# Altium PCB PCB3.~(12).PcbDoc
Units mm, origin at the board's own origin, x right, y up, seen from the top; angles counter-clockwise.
Board outline 50 x 50 mm, 4 copper layers (Top Layer, Internal Plane 1, Internal Plane 2, Bottom Layer), stack 0.462 mm thick; 11 components, 12 nets, 36 pads, 0 vias.
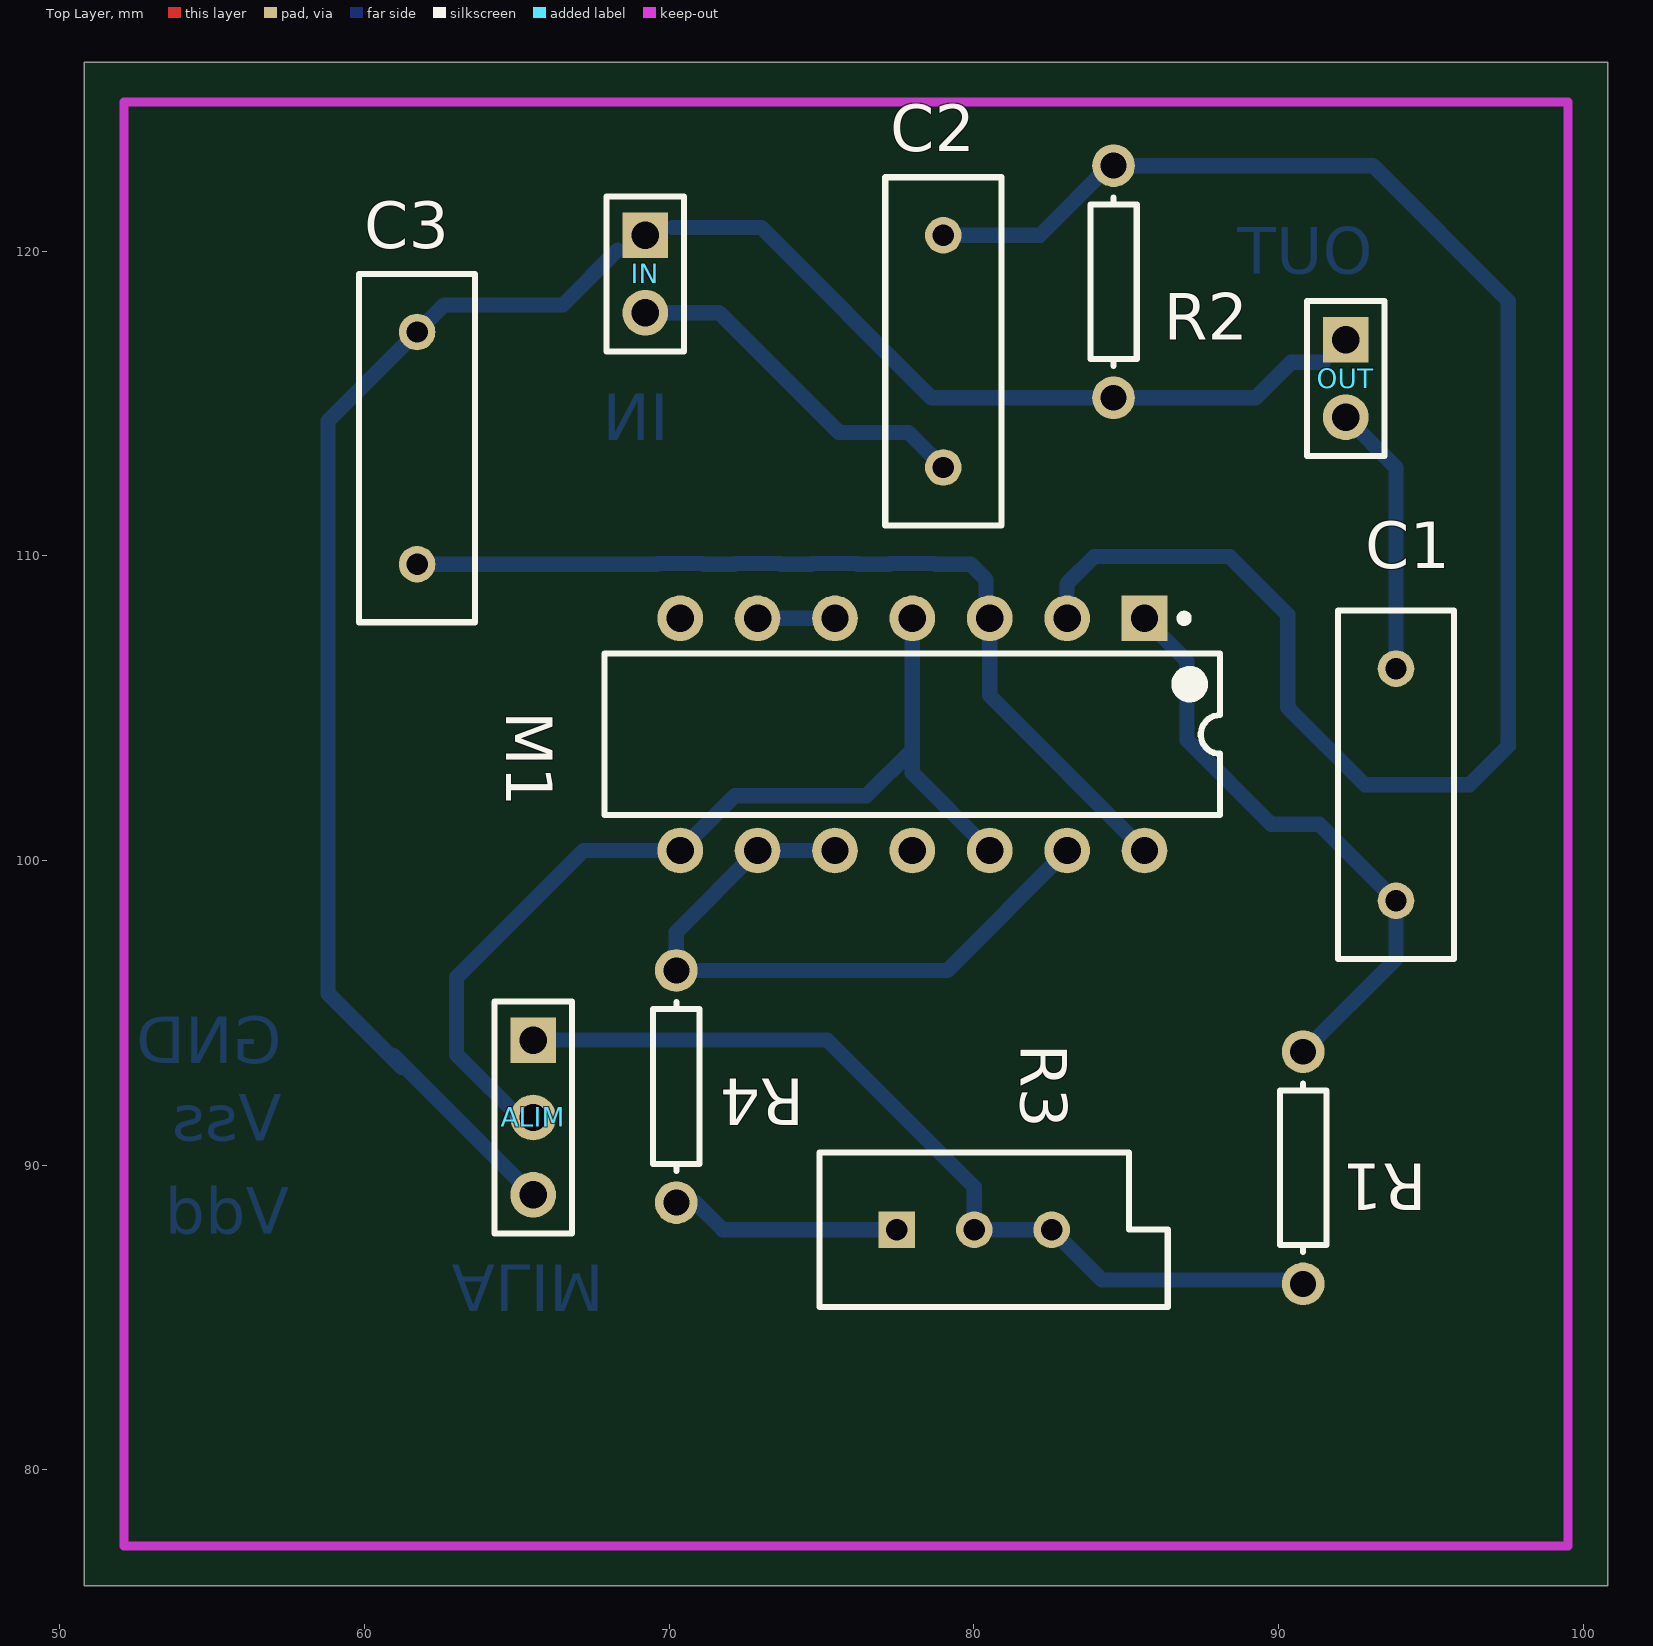
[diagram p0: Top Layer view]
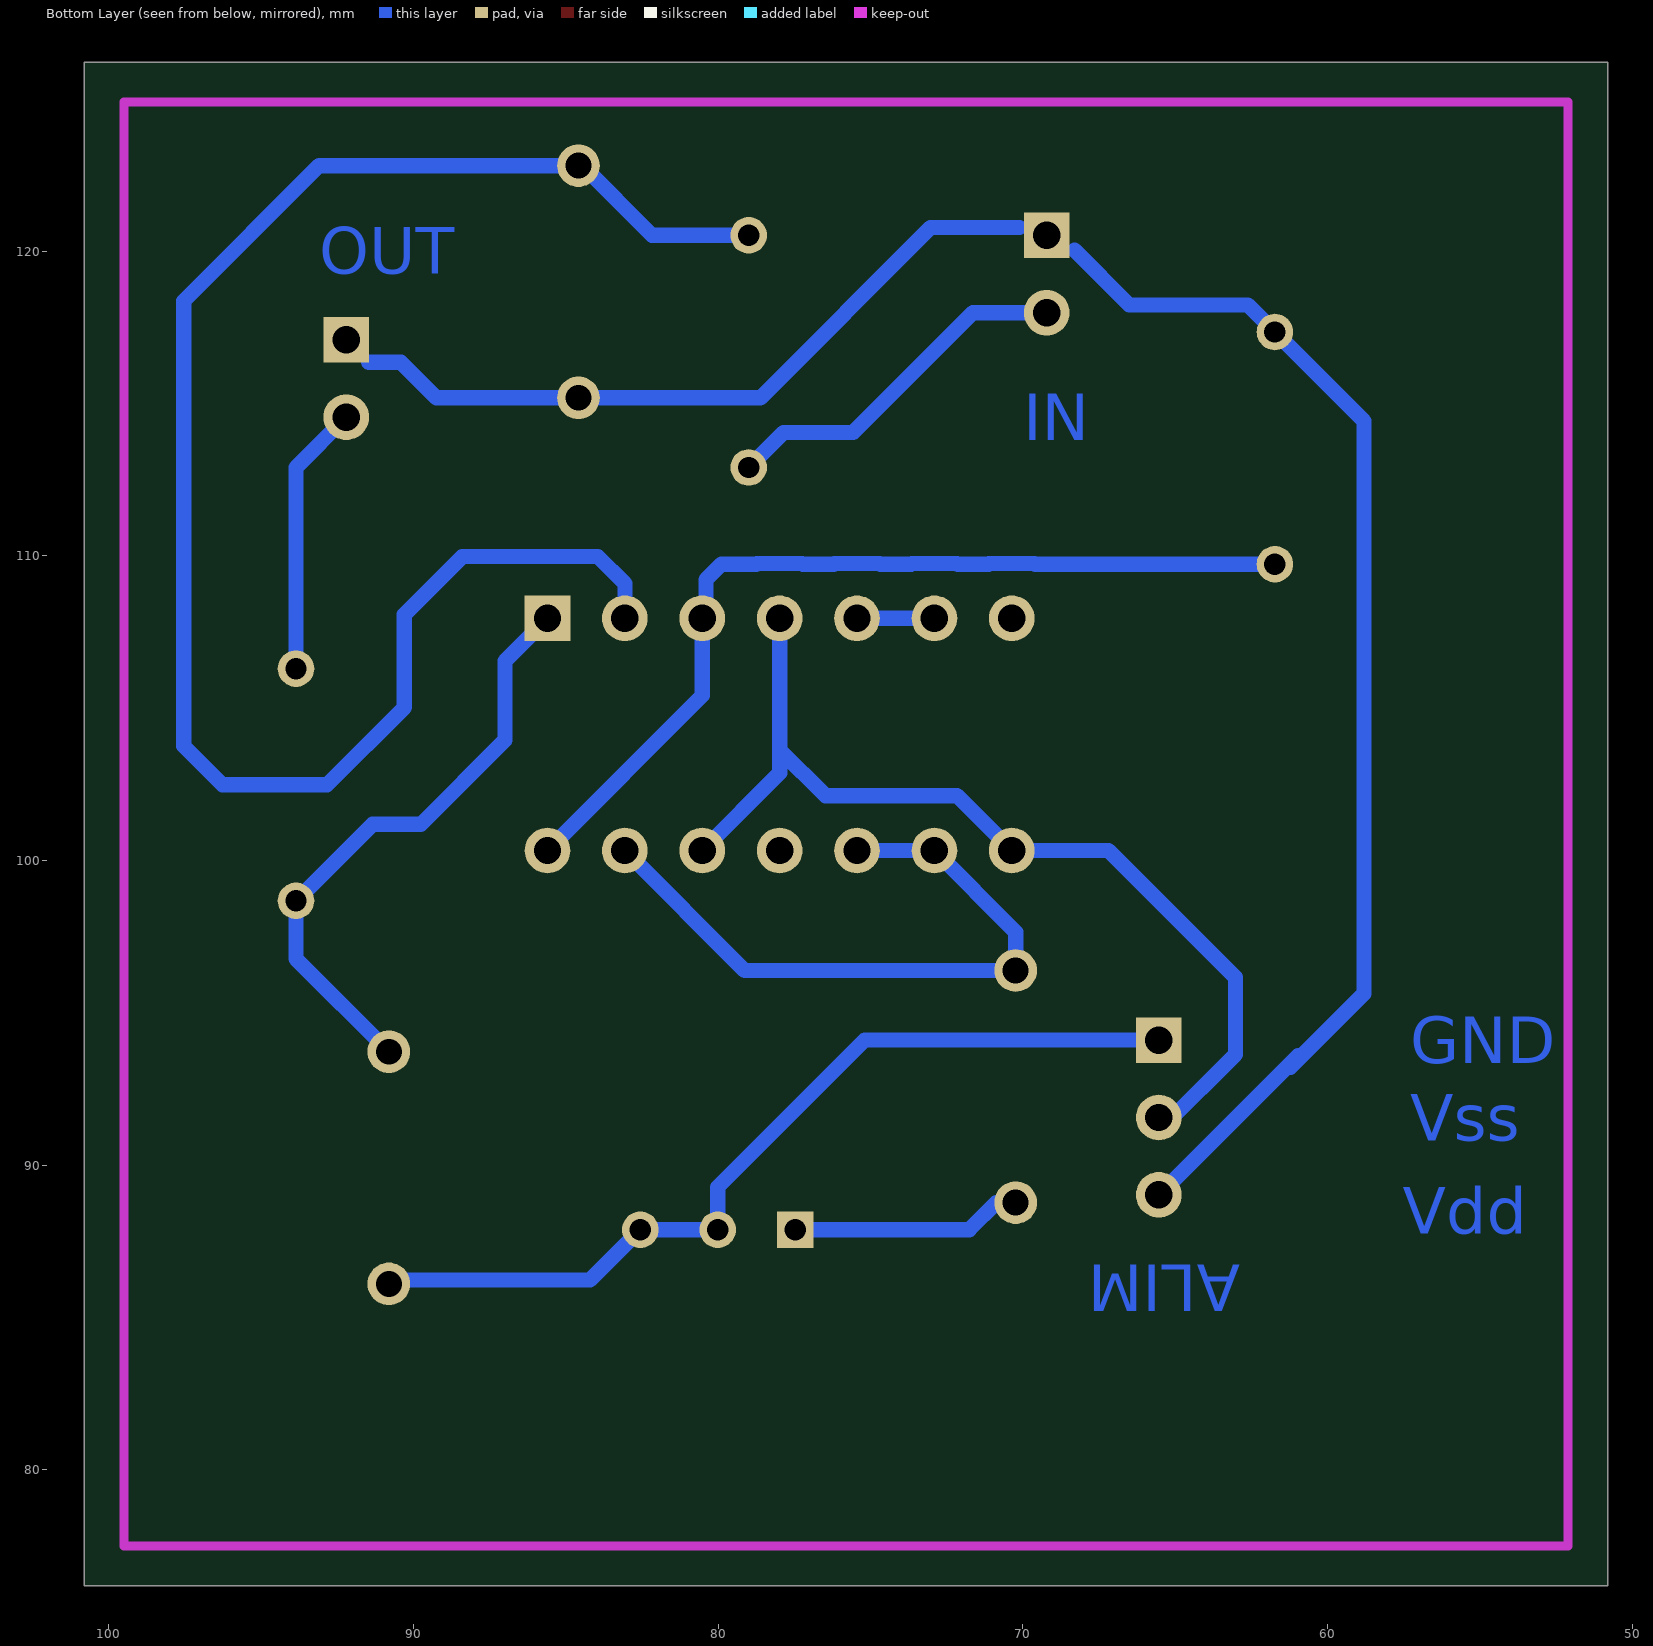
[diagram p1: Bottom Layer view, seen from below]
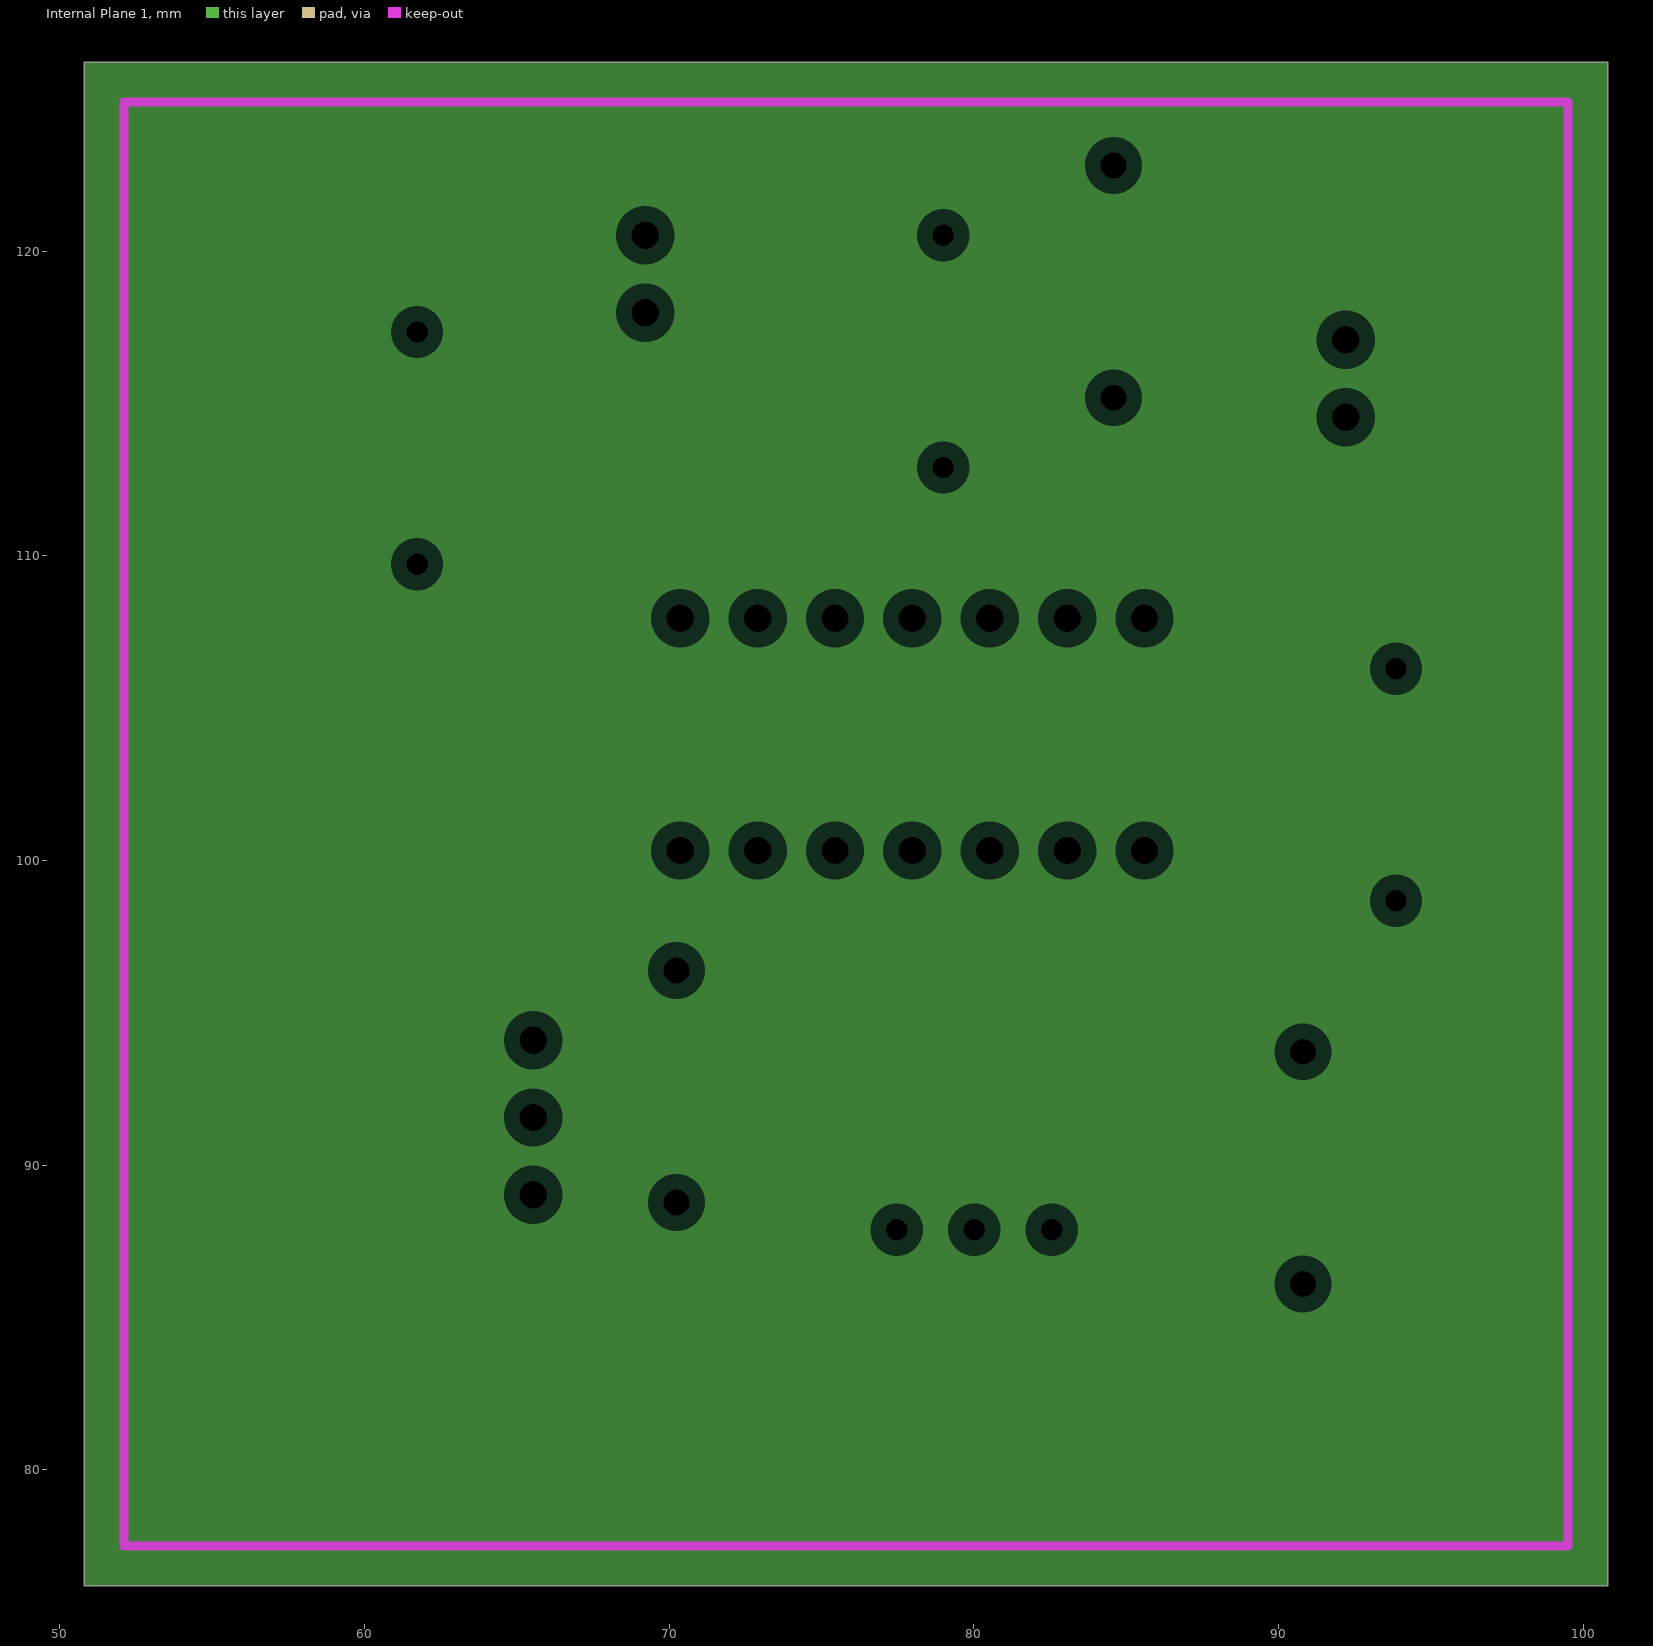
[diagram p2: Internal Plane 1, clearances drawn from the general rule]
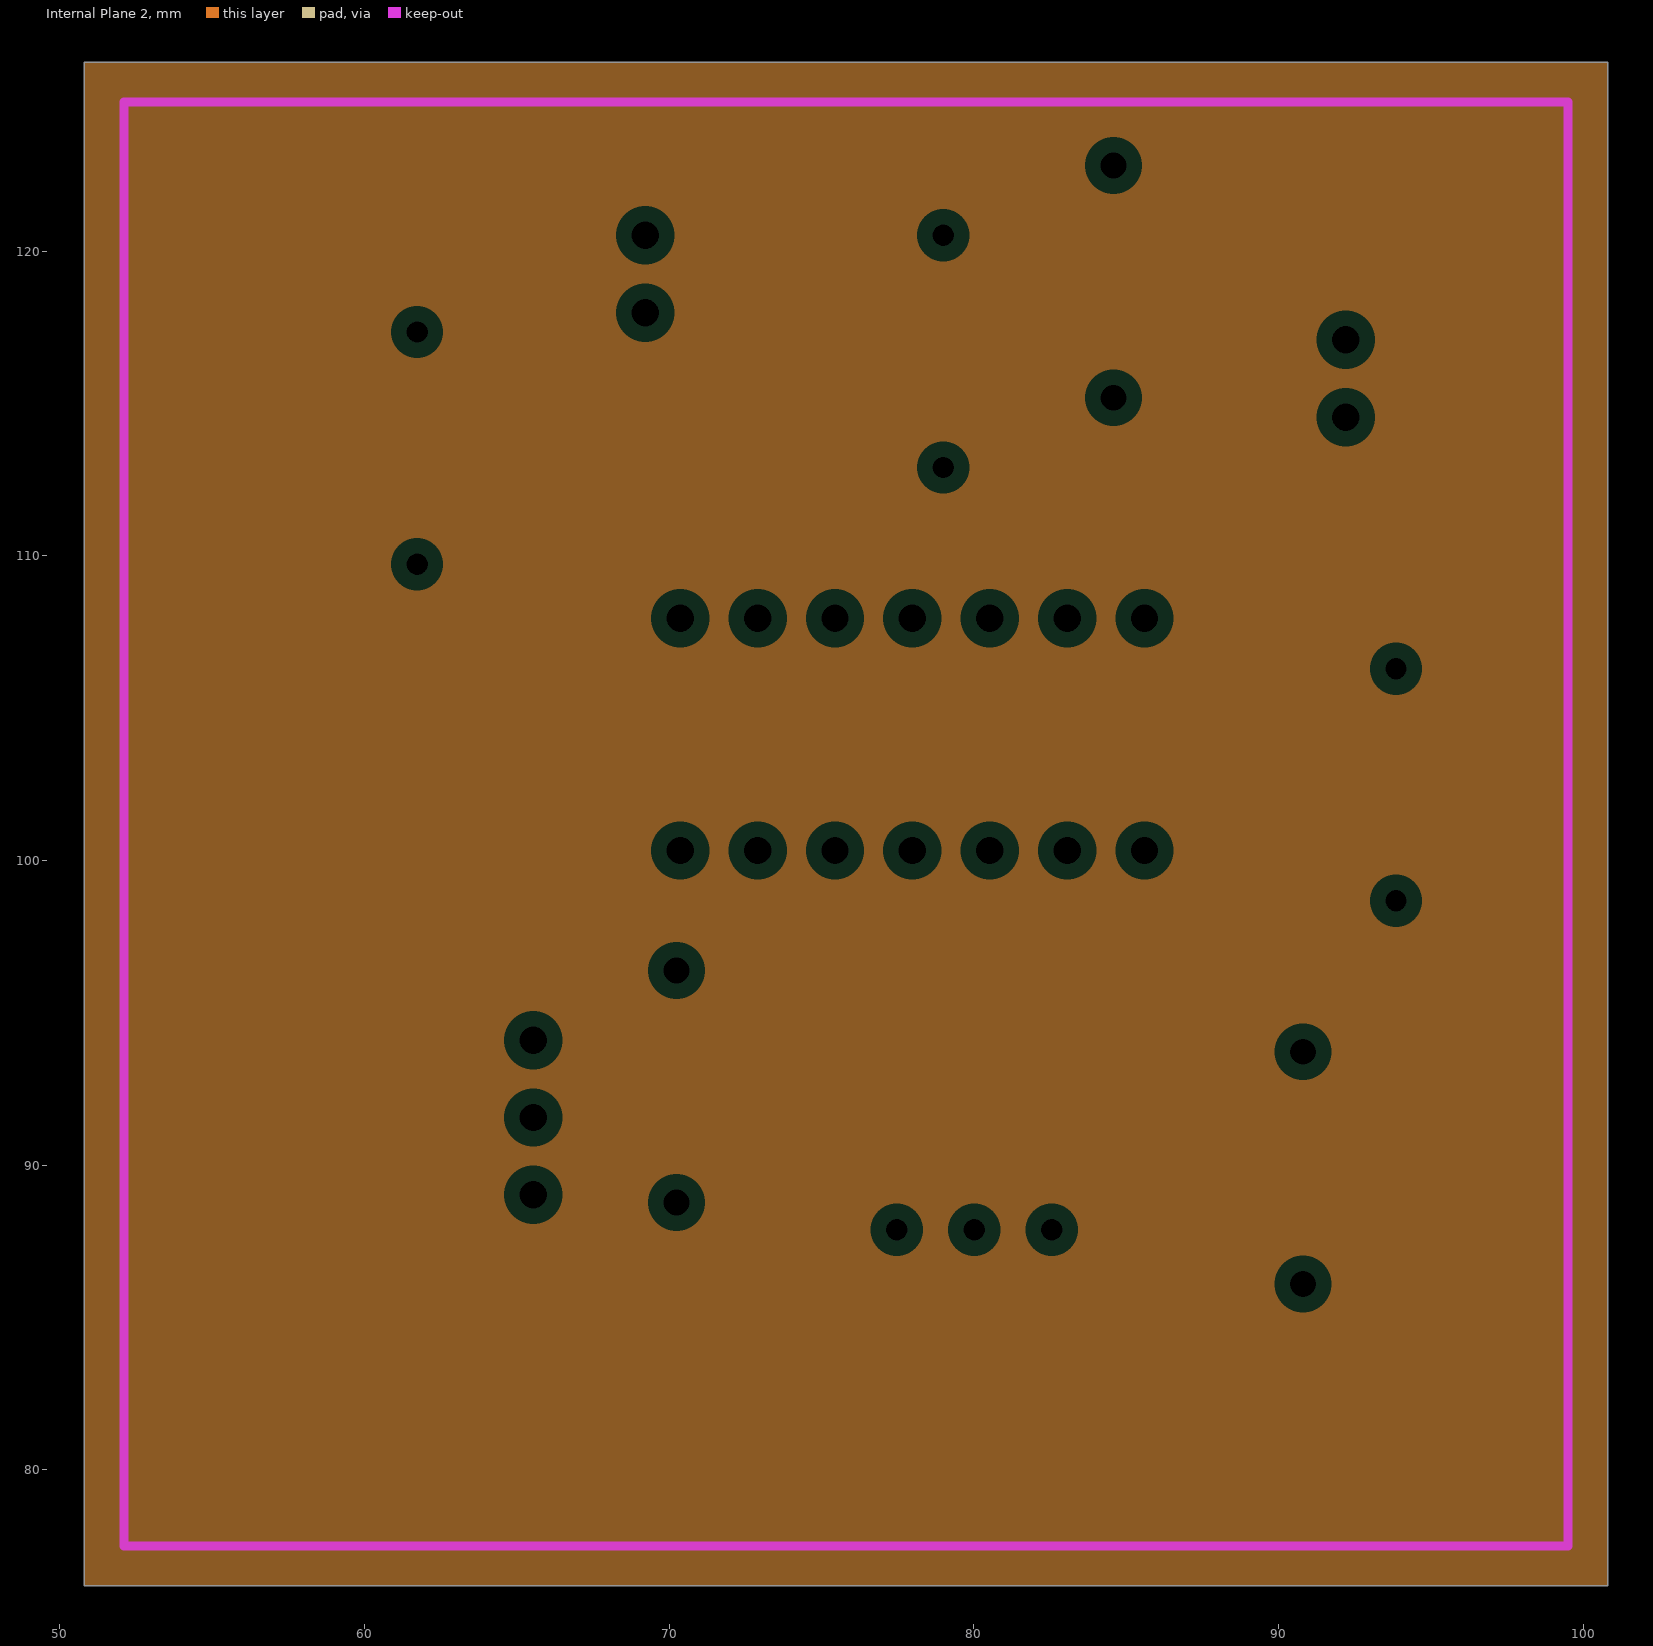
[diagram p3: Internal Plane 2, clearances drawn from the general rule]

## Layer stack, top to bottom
Top Solder: solder mask 0.0102, Solder Resist, Dk 3.5
Top Layer: signal copper 0.0356
Internal Plane 1: plane copper 0.0356
Internal Plane 2: plane copper 0.0356
Dielectric 1: dielectric 0.32, FR-4, Dk 4.8
Bottom Layer: signal copper 0.0356
Bottom Solder: solder mask 0.0102, Solder Resist, Dk 3.5

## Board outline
50.8,76.2 100.8,76.2 100.8,126.2 50.8,126.2

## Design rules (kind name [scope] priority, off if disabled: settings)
Clearance [All] p1: gap=0.8
PlaneClearance [All] p1: clearance=0.508
PlaneConnect [All] p1: planeconnectstyle=Relief reliefexpansion=0.508 reliefentries=4 reliefconductorwidth=0.254 reliefairgap=0.254
PolygonConnect [All] p1: connectstyle=Relief reliefconductorwidth=0.254 reliefentries=4 polygonreliefangle="90 Angle" airgapwidth=0.254
RoutingVias [All] p1: holewidth=0.8 width=1.6 viastyle="Through Hole" minholewidth=0.711 minwidth=1.27 maxholewidth=0.711 maxwidth=1.27
SolderMaskExpansion [All] p1: expansion=0.102
Width [All] p1: maxlimit=0.5 minlimit=0.5 preferedwidth=0.5
28 further rules are at their usual default settings.

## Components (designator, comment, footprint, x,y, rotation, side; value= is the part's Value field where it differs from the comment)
ALIM "Header 3" HDR1X3 65.532,94.107 r270 top
C1 "Cap" RAD-0.3 93.853,102.489 r90 top
C2 "Cap" RAD-0.3 78.994,116.713 r90 top
C3 "Cap" RAD-0.3 61.722,113.538 r90 top
IN "IN" HDR1X2 69.215,120.523 r270 top
M1 "ALD1106" DIP-14 77.978,104.14 r270 top
OUT "OUT" HDR1X2 92.202,117.094 r270 top (schematic designator Out)
R1 "Res1" AXIAL-0.3 90.805,89.916 r270 top
R2 "Res1" AXIAL-0.3 84.582,118.999 r90 top
R3 "RPot" VR5 80.01,87.884 r0 top
R4 "Res1" AXIAL-0.3 70.231,92.583 r270 top

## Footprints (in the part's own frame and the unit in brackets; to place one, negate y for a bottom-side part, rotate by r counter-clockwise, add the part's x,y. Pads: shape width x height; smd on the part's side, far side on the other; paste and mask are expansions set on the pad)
AXIAL-0.3 [mm] "Axial Device, Thru-Hole; 2 Leads; 0.3 in Pin Spacing"
  round 1.4 hole 0.85: 1(-3.81,0) 2(3.81,0)
  silkscreen extent -2.77,-0.76 2.77,0.76
DIP-14 [mm] "DIP, 14-Pin, Row Spacing 7.62 mm, Pitch 2.54 mm"
  rect 1.5x1.5 hole 0.9: 1(-3.81,7.62)
  round 1.5 hole 0.9: 2(-3.81,5.08) 3(-3.81,2.54) 4(-3.81,0) 5(-3.81,-2.54) 6(-3.81,-5.08) 7(-3.81,-7.62) 8(3.81,-7.62) 9(3.81,-5.08) 10(3.81,-2.54) 11(3.81,0) 12(3.81,2.54) 13(3.81,5.08) 14(3.81,7.62)
  silkscreen extent -3.93,-10.1 2.65,10.1, body extent -3.6,-10.1 3.6,10.1, height 5.08
HDR1X2 [mm] "Connector; Header; 2 Position"
  rect 1.5x1.5 hole 0.9: 1(0,0)
  round 1.5 hole 0.9: 2(2.54,0)
  silkscreen extent -1.27,-1.27 3.81,1.27
HDR1X3 [mm] "Connector; Header; 3 Position"
  rect 1.5x1.5 hole 0.9: 1(0,0)
  round 1.5 hole 0.9: 2(2.54,0) 3(5.08,0)
  silkscreen extent -1.27,-1.27 6.35,1.27
RAD-0.3 [mm] "Radial Cap, Thru-Hole; 2 Leads; 0.3 in Pin Spacing"
  round 1.2 hole 0.7: 1(-3.81,0) 2(3.81,0)
  silkscreen extent -5.71,-1.91 5.71,1.91
VR5 [mm] "Thru-Hole; 3 Leads"
  rect 1.2x1.2 hole 0.7: 1(-2.54,0)
  round 1.2 hole 0.7: 2(0,0) 3(2.54,0)
  silkscreen extent -5.08,-2.54 6.35,2.54

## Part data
ALIM: "Header, 3-Pin"
C1 C2 C3: "Capacitor"
IN OUT: library part "Header 2", "Header, 2-Pin"
M1: "Quad N-channel matched MOSFET array"
R1 R2 R4: "Resistor"
R3: "Potentiometer"

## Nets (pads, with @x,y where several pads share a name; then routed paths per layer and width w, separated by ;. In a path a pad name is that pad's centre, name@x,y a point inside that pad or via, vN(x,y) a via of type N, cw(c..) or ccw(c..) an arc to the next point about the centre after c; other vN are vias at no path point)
GND: ALIM.3 C3.2 IN.1 OUT.1 R2.1 | length 64.3
  Bottom Layer w0.5: 60.954,93.599 65.526,89.027 ALIM.3 ; 61.214,93.218 58.801,95.631 58.801,114.427 C3.2 62.611,118.237 66.504,118.237 68.304,120.037 ; 70.104,120.777 73.025,120.777 78.613,115.189 R2.1@84.201,115.189 ; R2.1 89.237,115.189 90.402,116.354 OUT.1@91.462,116.354
NetALIM_1: ALIM.1 R1.2 R3.2 R3.3 | length 29.5
  Bottom Layer w0.5: ALIM.1 75.184,94.107 80.01,89.281 R3.2 R3.3 84.201,86.233 R1.2@90.678,86.233 ; R1.2@90.551,86.106 R1.2
NetALIM_2: ALIM.2 M1.4 M1.8 M1.12 | length 32.5
  Bottom Layer w0.5: ALIM.2@65.31,91.345 63.019,93.635 63.019,96.166 67.183,100.33 M1.8 70.358,100.336 72.152,102.13 76.476,102.13 77.978,103.632 ; M1.4 77.978,103.632 ; M1.12 80.518,100.336 77.978,102.876 77.978,103.632
NetC1_1: C1.1 M1.1 R1.1 | length 19.8
  Bottom Layer w0.5: M1.1 86.995,106.553 86.995,105.918 86.995,103.953 89.759,101.189 91.343,101.189 C1.1 93.853,96.774 R1.1
NetC1_2: C1.2 OUT.2 | length 8.9
  Bottom Layer w0.5: OUT.2 93.853,112.903 C1.2
NetC2_1: C2.1 IN.2 | length 11.9
  Bottom Layer w0.5: IN.2 71.628,117.983 75.565,114.046 77.851,114.046 C2.1
NetC2_2: C2.2 M1.2 R2.2 | length 57.2
  Bottom Layer w0.5: C2.2 82.169,120.523 R2.2@84.455,122.809 ; M1.2 83.058,109.093 83.947,109.982 88.392,109.982 90.297,108.077 90.297,105.029 92.837,102.489 96.266,102.489 97.536,103.759 97.536,118.364 93.091,122.809 R2.2
NetC3_1: C3.1 M1.3 M1.14 | length 29.7
  Bottom Layer w0.5: C3.1 69.59,109.728 69.612,109.75 71.104,109.75 71.126,109.728 72.13,109.728 72.152,109.75 73.644,109.75 73.666,109.728 74.67,109.728 74.692,109.75 76.184,109.75 76.206,109.728 77.21,109.728 77.232,109.75 78.724,109.75 78.746,109.728 79.883,109.728 80.391,109.22 M1.3@80.391,108.204 ; M1.3 80.518,105.416 M1.14@85.598,100.336
NetM1_4: M1.7
NetM1_5: M1.5 M1.6 | length 2.6
  Bottom Layer w0.5: M1.6@72.898,107.988 M1.6 M1.5
NetM1_9: M1.9 M1.10 M1.13 R4.1 | length 22
  Bottom Layer w0.5: M1.9@72.898,100.324 70.231,97.657 R4.1 79.127,96.393 83.058,100.324 M1.13 ; M1.9 M1.10
NetR3_1: R3.1 R4.2 | length 7
  Bottom Layer w0.5: R4.2@70.866,88.773 71.755,87.884 R3.1
pads on no net: M1.11

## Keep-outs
Keep-Out Layer:
  lines w0.3: 52.1,77.5 52.1,124.9 99.5,124.9 99.5,77.5 52.1,77.5

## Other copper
Bottom Layer:
  text "GND" at 57.277,93.345 h1.52
  text "Vss" at 57.277,90.805 h1.52
  text "Vdd" at 57.531,87.757 h1.52

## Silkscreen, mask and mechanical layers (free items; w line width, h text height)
Drill Drawing:
  text "William Zheng" at 53.594,82.169 h1.52
  text "Nathan Cuvelliez" at 53.721,79.375 h1.52

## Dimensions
52.1,77.5 to 52.1,124.9 on Mechanical 1
52.1,77.5 to 99.5,77.5 on Mechanical 1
